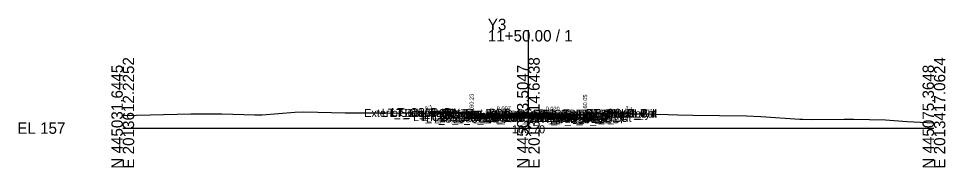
# Model space of a CAD drawing. Extents: x -26 to 203, y -10 to 5017.
# Drawn here: x -25.7 to 202.8, y 2990.3 to 3027 of the extents above; entities that cross this region are included whole.
import ezdxf

# ---------------------------------------------------------------- set-up
doc = ezdxf.new("R2010")
doc.units = 0
for name, color, linetype in [('Default', 7, 'Continuous'), ('Exist Cross Section Cell', 7, 'Continuous'), ('Exist XS Center Line Elevation Label', 7, 'Continuous'), ('Exist XS Ground Line', 7, 'Continuous'), ('Prop CMT Conc Surface', 7, 'Continuous'), ('Prop CMT Concrete Structures', 7, 'Continuous'), ('Prop CMT Pvmt Course 1', 7, 'Continuous'), ('Prop CMT Pvmt Course 1 CG', 7, 'Continuous'), ('Prop CMT Pvmt Course 2', 7, 'Continuous'), ('Prop CMT Pvmt Course 3', 7, 'Continuous'), ('Prop CMT Pvmt Surface', 7, 'Continuous'), ('Prop CMT Slope Grass', 7, 'Continuous'), ('Prop CMT Subgrade Earthwork', 7, 'Continuous'), ('Prop XS Earthwork Shape', 7, 'Continuous'), ('Prop XS Hydro Elevations', 7, 'Continuous'), ('Prop XS SE Text', 7, 'Continuous'), ('Prop XS Side Slope Text', 7, 'Continuous'), ('Scratch_Level_0', 7, 'Continuous')]:
    doc.layers.add(name, color=color, linetype=linetype)

msp = doc.modelspace()

# ---------------------------------------------------------------- linework, layer by layer
at = {"layer": 'Exist Cross Section Cell'}
for p, q in [((100, 3000), (100, 3024.14)), ((0, 3000), (100, 3000)), ((100, 3000), (200, 3000))]:
    msp.add_line(p, q, dxfattribs=at)
at = {"layer": 'Exist XS Ground Line'}
msp.add_lwpolyline([(0, 3003.06), (0.06, 3003.07), (16.77, 3003.48), (24.44, 3003.49), (32.53, 3003.28), (34.02, 3003.25), (34.36, 3003.25), (42.4, 3003.95), (44.61, 3003.98), (48.09, 3003.93), (54.86, 3003.76), (61.3, 3003.73), (65.11, 3003.73), (74.76, 3003.71), (78.46, 3003.73), (80.21, 3003.73), (80.58, 3003.72), (86.23, 3003.46), (87.24, 3003.24), (87.85, 3003.15), (98.15, 3003.64), (100, 3003.7), (101.12, 3003.74), (102.98, 3003.67), (112.08, 3003.24), (112.44, 3003.29), (113.42, 3003.46), (115.85, 3003.48), (118.3, 3003.75), (121.2, 3003.66), (134.5, 3003.32), (136.85, 3003.29), (140.55, 3003.19), (147.1, 3003.1), (153.76, 3002.99), (157.35, 3002.84), (166.96, 3002.18), (167.6, 3002.16), (169.79, 3002.14), (177.85, 3002.2), (180.17, 3002.16), (188.09, 3002), (193.38, 3001.65), (198.34, 3001.38), (200, 3001.33)], dxfattribs=at)
at = {"layer": 'Prop CMT Conc Surface'}
for points in [[(86, 3003.23), (86, 3003.73), (85.5, 3003.73)], [(88, 3003.32), (86, 3003.23)], [(112, 3003.17), (114, 3003.05)], [(114, 3003.05), (114, 3003.55), (114.5, 3003.55)]]:
    msp.add_lwpolyline(points, dxfattribs=at)
at = {"layer": 'Prop CMT Concrete Structures'}
for points in [[(88, 3003.32), (86, 3003.23), (86, 3003.73), (85.5, 3003.73)], [(85.5, 3003.73), (85.5, 3002.72), (88, 3002.74)], [(88, 3002.74), (88, 3003.32)], [(112, 3003.17), (114, 3003.05), (114, 3003.55), (114.5, 3003.55)], [(114.5, 3003.55), (114.5, 3002.53), (112, 3002.58)], [(112, 3002.58), (112, 3003.17)]]:
    msp.add_lwpolyline(points, dxfattribs=at)
at = {"layer": 'Prop CMT Pvmt Course 1'}
for points in [[(100, 3003.41), (88, 3003.32)], [(88, 3003.32), (88, 3003.07)], [(88, 3003.07), (100, 3003.16)], [(100, 3003.16), (100, 3003.41)], [(100, 3003.41), (112, 3003.17)], [(100, 3003.16), (100, 3003.41)], [(112, 3002.92), (100, 3003.16)], [(112, 3003.17), (112, 3002.92)]]:
    msp.add_lwpolyline(points, dxfattribs=at)
msp.add_lwpolyline([(100, 3003.16), (100, 3003.28), (100, 3003.28), (100, 3003.16)], close=True, dxfattribs=at)
msp.add_lwpolyline([(100, 3003.16), (100, 3003.28), (100, 3003.28), (100, 3003.16)], close=True, dxfattribs=at)
at = {"layer": 'Prop CMT Pvmt Course 1 CG'}
for points in [[(88, 3002.74), (85, 3002.72), (84.66, 3002.38)], [(84.66, 3002.38), (88, 3002.41)], [(88, 3002.41), (88, 3002.74)], [(112, 3002.58), (115, 3002.52), (115.34, 3002.18)], [(112, 3002.25), (112, 3002.58)], [(115.34, 3002.18), (112, 3002.25)]]:
    msp.add_lwpolyline(points, dxfattribs=at)
at = {"layer": 'Prop CMT Pvmt Course 2'}
for points in [[(100, 3003.16), (88, 3003.07)], [(88, 3003.07), (88, 3002.74)], [(100, 3002.82), (100, 3003.16)], [(100, 3002.82), (100, 3003.16)], [(100, 3003.16), (112, 3002.92)], [(88, 3002.74), (100, 3002.82)], [(112, 3002.58), (100, 3002.82)], [(112, 3002.92), (112, 3002.58)]]:
    msp.add_lwpolyline(points, dxfattribs=at)
at = {"layer": 'Prop CMT Pvmt Course 3'}
for points in [[(100, 3002.82), (88, 3002.74)], [(88, 3002.74), (88, 3002.41)], [(88, 3002.41), (100, 3002.49)], [(100, 3002.49), (100, 3002.82)], [(100, 3002.82), (112, 3002.58)], [(100, 3002.49), (100, 3002.82)], [(112, 3002.25), (100, 3002.49)], [(112, 3002.58), (112, 3002.25)]]:
    msp.add_lwpolyline(points, dxfattribs=at)
at = {"layer": 'Prop CMT Pvmt Surface'}
for points in [[(100, 3003.41), (88, 3003.32)], [(100, 3003.41), (112, 3003.17)]]:
    msp.add_lwpolyline(points, dxfattribs=at)
at = {"layer": 'Prop CMT Slope Grass'}
for points in [[(85.5, 3003.73), (76, 3003.92), (75.39, 3003.72)], [(114.5, 3003.55), (124, 3003.74), (124.48, 3003.58)]]:
    msp.add_lwpolyline(points, dxfattribs=at)
at = {"layer": 'Prop CMT Subgrade Earthwork'}
for points in [[(88, 3002.41), (84.66, 3002.38), (83.27, 3003.77)], [(112, 3002.25), (115.34, 3002.18), (116.75, 3003.59)], [(100, 3002.49), (88, 3002.41)], [(100, 3002.49), (112, 3002.25)]]:
    msp.add_lwpolyline(points, dxfattribs=at)
at = {"layer": 'Prop XS Earthwork Shape'}
for points in [[(75.39, 3003.72), (78.46, 3003.73), (80.21, 3003.73), (80.58, 3003.72), (83.46, 3003.59), (83.27, 3003.77), (76, 3003.92)], [(112, 3002.25), (115.34, 3002.18), (116.73, 3003.57), (115.85, 3003.48), (114.5, 3003.47), (114.5, 3002.53), (112, 3002.58), (112, 3003.17), (100, 3003.41), (92.14, 3003.35), (88, 3003.15), (88, 3002.74), (85.5, 3002.72), (85.5, 3003.5), (83.46, 3003.59), (84.66, 3002.38), (88, 3002.41), (100, 3002.49)], [(88, 3002.74), (88, 3003.15), (87.85, 3003.15), (87.24, 3003.24), (87.07, 3003.28), (86, 3003.23), (86, 3003.47), (85.5, 3003.5), (85.5, 3002.72)], [(87.07, 3003.28), (86, 3003.23), (86, 3003.47), (86.23, 3003.46)], [(112, 3003.17), (114, 3003.05), (114, 3003.46), (113.42, 3003.46), (112.44, 3003.29), (112.08, 3003.24), (102.98, 3003.67), (101.12, 3003.74), (100, 3003.7), (98.15, 3003.64), (92.14, 3003.35), (100, 3003.41)], [(112, 3002.58), (112, 3003.17), (114, 3003.05), (114, 3003.46), (114.5, 3003.47), (114.5, 3002.53)], [(116.73, 3003.57), (116.93, 3003.6), (116.75, 3003.59)], [(116.93, 3003.6), (118.3, 3003.75), (120.78, 3003.67)], [(120.78, 3003.67), (124, 3003.74), (124.48, 3003.58), (121.2, 3003.66)]]:
    msp.add_lwpolyline(points, close=True, dxfattribs=at)

# ---------------------------------------------------------------- texts
at = {"layer": 'Default'}
msp.add_text('-', height=0.0001, dxfattribs=at).set_placement((0, 3000))
at = {"layer": 'Exist Cross Section Cell'}
for s, p in [('Y3', (90, 3024.14)), ('11+50.00 / 1', (90, 3021.34)), ('EL 157', (-26, 2998.6))]:
    msp.add_text(s, height=2.8, dxfattribs=at).set_placement(p)
for s, p in [('E 2013612.2252', (2.8, 2990)), ('E 2013514.6438', (102.8, 2990)), ('E 2013417.0624', (202.8, 2990)), ('N 445031.6445', (0, 2990)), ('N 445053.5047', (100, 2990)), ('N 445075.3648', (200, 2990))]:
    msp.add_text(s, height=2.8, rotation=90, dxfattribs=at).set_placement(p)
at = {"layer": 'Exist XS Center Line Elevation Label'}
msp.add_text('160.70', height=2, dxfattribs=at).set_placement((95.95, 2998.7))
at = {"layer": 'Prop XS Hydro Elevations'}
for s, p in [('160.23', (86.5, 3004.23)), ('160.05', (114.5, 3004.05))]:
    msp.add_text(s, height=1, rotation=90, dxfattribs=at).set_placement(p)
at = {"layer": 'Prop XS SE Text'}
for s, rotation, p in [('0.007', 0.4092, (92.24, 3004.35)), ('0.020', 358.8542, (104.27, 3004.32))]:
    msp.add_text(s, height=1, rotation=rotation, dxfattribs=at).set_placement(p)
at = {"layer": 'Prop XS Side Slope Text'}
for rotation, p in [(18.4332, (74.71, 3004.28)), (341.5668, (123.73, 3004.62)), (341.5668, (123.73, 3004.62))]:
    msp.add_text('3:1', height=1, rotation=rotation, dxfattribs=at).set_placement(p)
at = {"layer": 'Scratch_Level_0'}
for s, p in [('Exterior Boundary', (59.53, 3002.72)), ('LT_Sub_Trench_Out_DLT', (63.84, 3002.77)), ('LT_Slope_Fill', (65.91, 3002.72)), ('LT_CSLP_Pnt', (66.17, 3002.92)), ('LT_CG1_Shelf_Out', (71.55, 3001.72)), ('LT_CG_Top_Face', (73.26, 3002.73)), ('LT_CG_Top_BOC', (73.78, 3002.73)), ('LT_CG_Bot_BOC', (73.81, 3001.72)), ('LT_CG_Top_Gut', (74.24, 3002.23)), ('LT_Sub_OEOP', (74.77, 3001.38)), ('LT_CG_Bot_IE', (77.91, 3001.74)), ('LT_Sub_OEOT', (78.08, 3001.41)), ('LT_PV2_OEOT', (78.17, 3002.07)), ('LT_PV3_OEOT', (78.17, 3001.74)), ('LT_PV1_OEOT', (78.74, 3002.32)), ('RT_Sub_OEEOP', (89.17, 3001.49)), ('LT_Sub_OEEOP', (89.21, 3001.49)), ('RT_PV2_OEEOP', (89.26, 3002.16)), ('RT_PV3_OEEOP', (89.26, 3001.82)), ('LT_PV2_OEEOP', (89.31, 3002.16)), ('LT_PV3_OEEOP', (89.31, 3001.82)), ('RT_PV1_OEEOP', (89.83, 3002.28)), ('LT_PV1_OEEOP', (89.87, 3002.28)), ('RT_PV2_IEEOP', (89.91, 3002.16)), ('LT_PV2_IEEOP', (89.95, 3002.16)), ('RT_PV1_IEEOP', (90.47, 3002.28)), ('LT_PV1_IEEOP', (90.52, 3002.28)), ('PV2_PGL', (93.91, 3002.16)), ('PV1_PGL', (94.47, 3002.41)), ('RT_Sub_Trench_Out_DLT', (97.27, 3002.59)), ('RT_CG_Top_Face', (101.21, 3002.55)), ('RT_CG1_Shelf_Out', (101.5, 3001.52)), ('RT_CG_Bot_IE', (101.87, 3001.58)), ('RT_Sub_OEOT', (102.03, 3001.25)), ('RT_PV2_OEOT', (102.13, 3001.92)), ('RT_PV3_OEOT', (102.13, 3001.58)), ('RT_CG_Top_Gut', (102.19, 3002.05)), ('RT_PV1_OEOT', (102.69, 3002.17)), ('RT_CG_Top_BOC', (102.74, 3002.55)), ('RT_CG_Bot_BOC', (102.77, 3001.53)), ('RT_Sub_OEOP', (105.4, 3001.18)), ('Exterior Boundary', (108.63, 3002.58)), ('RT_Slope_Cut', (114.08, 3002.58)), ('RT_CSLP_Pnt', (114.13, 3002.74)), ('RT_Slope_Fill', (114.96, 3002.58))]:
    msp.add_text(s, height=2, dxfattribs=at).set_placement(p)

doc.saveas('drawing.dxf')
